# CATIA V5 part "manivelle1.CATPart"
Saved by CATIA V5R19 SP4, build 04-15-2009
Part number: manivelle1
Bounding box of the stored display mesh (mm): x -6 to 7, y -25 to 25, z -24.818 to 24.818
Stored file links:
  E:\IAO_2010\iao\IAO_MMS_Groupe1\Problemes\tlampure\tlampure\tlampure\manivelle1.CATPart
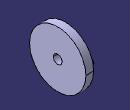
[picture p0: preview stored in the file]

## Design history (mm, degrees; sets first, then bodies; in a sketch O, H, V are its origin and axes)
Parameters
  R = 25 mm
  L1 = 16.1226 mm {= R -`détruit_LENGTH`}
Body1 (main body)
  Sketch1 on yz-plane, origin (0, 0, 0), H (0, 1, 0), V (0, 0, 1)
    circle A1 centre (0, 0) radius 25
    radius A1 = 25 {= R}
  Pad1: profile Sketch1, direction (1, 0, 0), length 7
  Sketch2 on yz-plane, origin (0, 0, 0), H (0, 1, 0), V (0, 0, 1)
    circle A1 centre (16.1226, 0) radius 3
    point P1 (16.1226, 0)
    distance O P1 = 16.1226 {= L1}
    coincidence: P1 H
  Pad2: profile Sketch2, direction (-1, 0, 0), length 6
  Sketch3 on yz-plane, origin (0, 0, 0), H (0, 1, 0), V (0, 0, 1)
    circle A1 centre (0, 0) radius 4
    point P1 (4, 0)
    coincidence: A1 P1, P1 H
  Pocket1: profile Sketch3, direction (1, 0, 0), length 10
  Sketch4 on start face of Pad1, origin (0, 0, 0), H (0, -1, 0), V (0, 0, 1)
